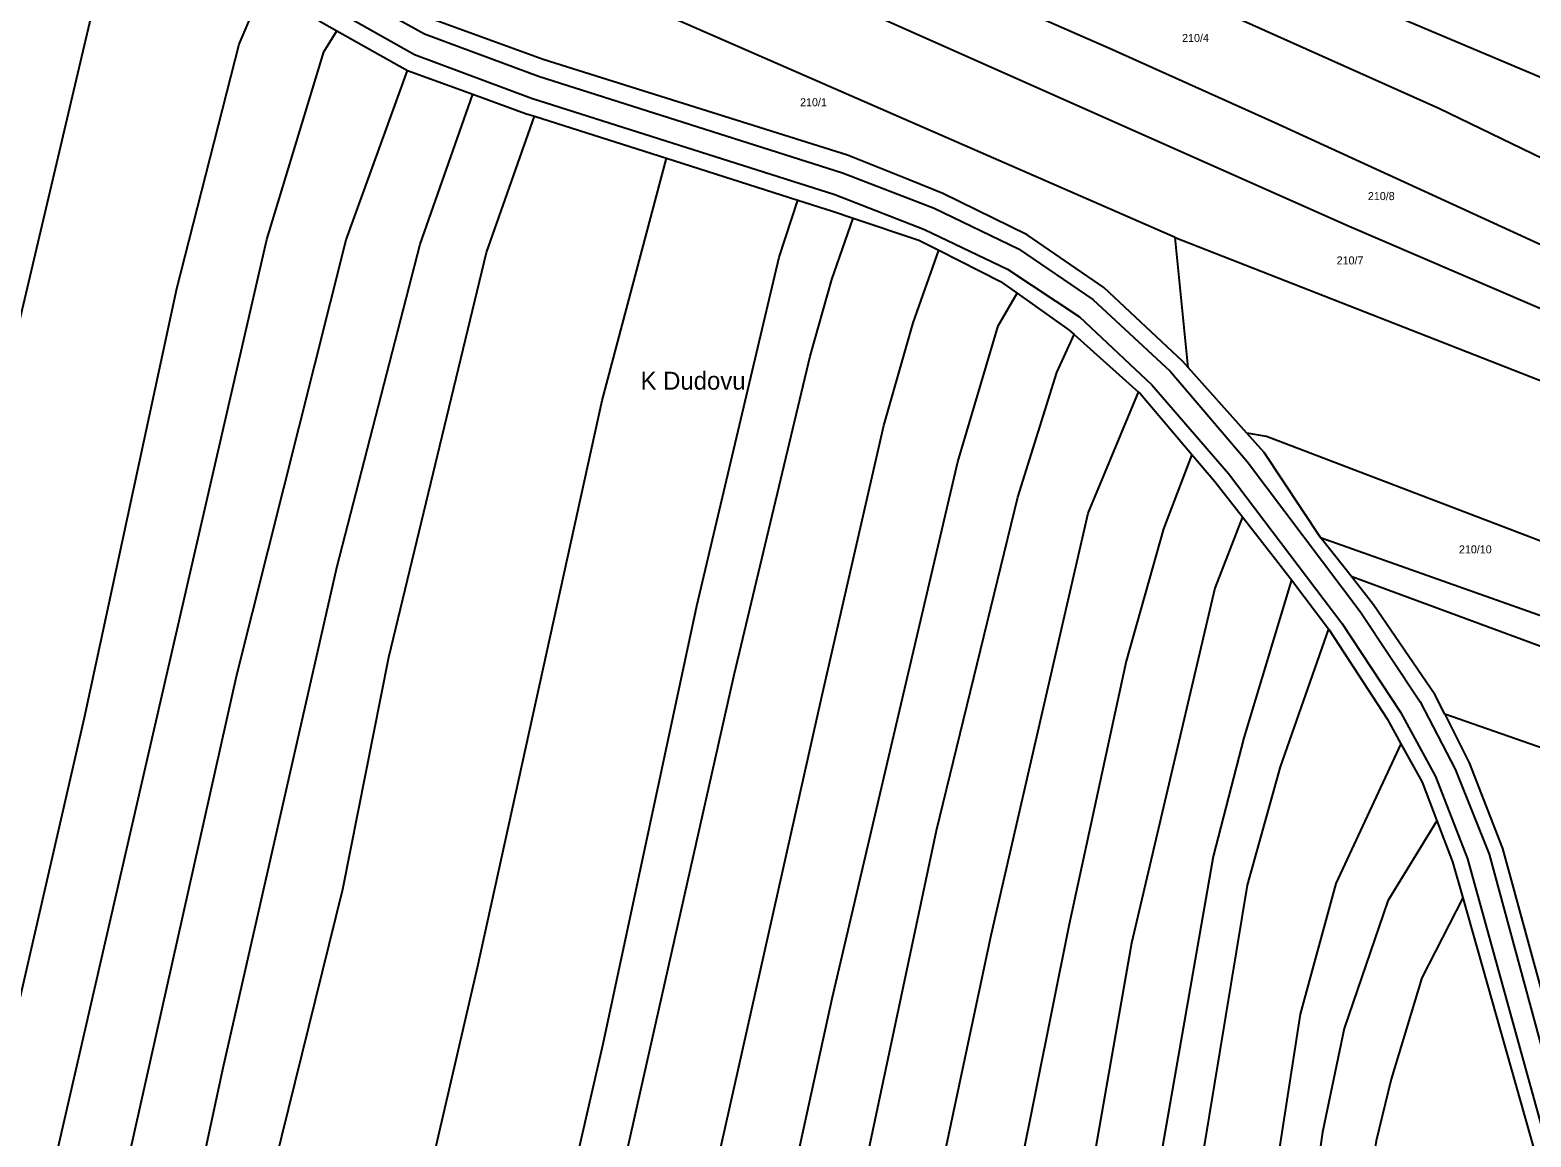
# Model space of a CAD drawing. Extents: x -744566 to -741843, y -1128407 to -1126744.
# Drawn here: x -743076.5 to -742757.6, y -1128024.5 to -1127789.3 of the extents above; entities that cross this region are included whole.
import ezdxf

# ---------------------------------------------------------------- set-up
doc = ezdxf.new("R2010")
doc.units = 0
for name, color, linetype in [('Hranice parcel', 7, 'Continuous'), ('Parcelní čísla', 7, 'Continuous'), ('Pop  PČ popisy', 7, 'Continuous'), ('Vnitřní kresba', 7, 'Continuous')]:
    doc.layers.add(name, color=color, linetype=linetype)

msp = doc.modelspace()

# ---------------------------------------------------------------- linework, layer by layer
at = {"layer": 'Hranice parcel'}
for p, q in [((-742833.19, -1127833.4), (-742972.27, -1127772.64)), ((-743011.33, -1127789.48), (-742996.28, -1127797.93)), ((-742996.28, -1127797.93), (-742982.41, -1127802.98)), ((-742969.31, -1127807.66), (-742941.27, -1127816.58)), ((-742941.27, -1127816.58), (-742913.36, -1127825.45)), ((-742830.43, -1127861.03), (-742833.19, -1127833.4)), ((-742854.64, -1127854.03), (-742840.94, -1127866.29)), ((-742817.94, -1127875.01), (-742830.43, -1127861.03)), ((-742802.25, -1127897.14), (-742686.17, -1127938.31)), ((-742795.76, -1127905.39), (-742802.25, -1127897.14)), ((-742808.46, -1127906.18), (-742800.6, -1127916.58)), ((-742795.76, -1127905.39), (-742687.4, -1127945.34)), ((-742698.39, -1127961.68), (-742775.86, -1127934.72)), ((-742772.05, -1127973.74), (-742745.25, -1128068.29))]:
    msp.add_line(p, q, dxfattribs=at)
for points in [[(-742705.33, -1127822.31), (-742752.11, -1127800.85), (-742855.88, -1127756.96), (-742856.57, -1127758.28), (-742916.95, -1127732.14)], [(-743134.48, -1128101.6), (-743116.84, -1128032.47), (-743112.87, -1128006.6), (-743093.99, -1127930.3), (-743081.3, -1127862.06), (-743057.88, -1127762.39), (-743049.21, -1127739.41)], [(-742929.76, -1127741.52), (-742892.25, -1127757.26), (-742839.56, -1127779.37), (-742839.56, -1127777.92), (-742777.16, -1127805.95), (-742712.92, -1127837.01)], [(-742942.9, -1127751.14), (-742921.78, -1127760.46), (-742847.12, -1127793.15), (-742812.02, -1127809), (-742724.3, -1127849.19), (-742701.43, -1127856.81), (-742666.84, -1127871.89)], [(-742670.28, -1127883.77), (-742733.59, -1127858.01), (-742796.71, -1127830.89), (-742912.22, -1127779.41), (-742955.04, -1127760.03)], [(-743103, -1128100.87), (-743064.96, -1127935.44), (-743045.29, -1127844.24), (-743032.09, -1127792.31), (-743025.38, -1127776.65)], [(-743025.38, -1127776.65), (-743015.05, -1127787.39), (-743011.33, -1127789.48)], [(-742830.43, -1127861.03), (-742831.55, -1127859.78), (-742848.33, -1127844.01), (-742864.61, -1127832.85), (-742882.56, -1127824.07), (-742889.66, -1127821.18), (-742902.77, -1127815.89), (-742967.48, -1127795.61), (-742991.64, -1127786.82)], [(-743087.22, -1128100.5), (-743078.12, -1128059.75), (-743051.52, -1127944.14), (-743026.17, -1127833.83), (-743014.07, -1127793.96), (-743011.33, -1127789.48)], [(-743071.48, -1128100.13), (-743055.35, -1128028.26), (-743032.57, -1127926.34), (-743009.32, -1127833.88), (-742996.28, -1127797.93)], [(-743054.77, -1128099.74), (-743035.44, -1128009.87), (-743011.3, -1127903.56), (-742993.62, -1127834.86), (-742982.41, -1127802.98)], [(-742982.41, -1127802.98), (-742971.25, -1127807.04), (-742969.31, -1127807.66)], [(-743039.34, -1128099.38), (-743028.83, -1128047.9), (-743010.01, -1127971.9), (-743000.24, -1127922.55), (-742979.49, -1127836.62), (-742969.31, -1127807.66)], [(-743006.9, -1128098.63), (-742981.41, -1127988.5), (-742954.92, -1127868.05), (-742941.27, -1127816.58)], [(-742976.11, -1128097.91), (-742954.73, -1128004.76), (-742934.78, -1127911.65), (-742917.32, -1127837.6), (-742913.36, -1127825.45)], [(-742913.36, -1127825.45), (-742905.98, -1127827.8), (-742901.58, -1127829.29)], [(-742965.39, -1128097.66), (-742926.85, -1127926.34), (-742910.73, -1127858.59), (-742906.15, -1127842.32), (-742901.58, -1127829.29)], [(-742901.58, -1127829.29), (-742887.63, -1127833.99), (-742883.39, -1127836.13)], [(-742833.19, -1127833.4), (-742726.08, -1127875.32), (-742678.13, -1127896.57), (-742675.1, -1127891.02)], [(-742945.48, -1128097.2), (-742908.25, -1127930.92), (-742895.08, -1127873.37), (-742888.84, -1127851.53), (-742883.39, -1127836.13)], [(-742883.39, -1127836.13), (-742870.31, -1127842.73), (-742866.75, -1127845.26)], [(-742928.33, -1128096.8), (-742906.05, -1127995.14), (-742879.36, -1127881.1), (-742870.77, -1127852.17), (-742866.75, -1127845.26)], [(-742866.75, -1127845.26), (-742855.66, -1127853.11), (-742854.64, -1127854.03)], [(-742912.92, -1128096.44), (-742883.88, -1127959.44), (-742866.58, -1127888.59), (-742858.3, -1127862.06), (-742854.64, -1127854.03)], [(-742896.59, -1128096.06), (-742872.27, -1127981.64), (-742851.64, -1127891.97), (-742840.94, -1127866.29)], [(-742840.94, -1127866.29), (-742840.54, -1127866.65), (-742829.62, -1127879.49)], [(-742683.5, -1127925.44), (-742813.75, -1127875.71), (-742817.94, -1127875.01)], [(-742802.25, -1127897.14), (-742814.27, -1127879.12), (-742817.94, -1127875.01)], [(-742829.62, -1127879.49), (-742835.64, -1127895.32), (-742843.58, -1127923.46), (-742855.73, -1127979.68), (-742869.71, -1128049.18), (-742880.65, -1128096.32)], [(-742829.62, -1127879.49), (-742824.72, -1127885.25), (-742818.84, -1127892.78)], [(-742818.84, -1127892.78), (-742824.75, -1127907.89), (-742842.47, -1127983.35), (-742854.91, -1128054.54), (-742864.87, -1128098.1)], [(-742818.84, -1127892.78), (-742810.82, -1127903.05), (-742808.46, -1127906.18)], [(-742808.46, -1127906.18), (-742818.57, -1127939.73), (-742825.08, -1127964.96), (-742840.18, -1128051.28), (-742849.78, -1128099.8)], [(-742775.86, -1127934.72), (-742777.97, -1127930.5), (-742791.02, -1127911.43), (-742795.76, -1127905.39)], [(-742800.6, -1127916.58), (-742810.82, -1127945.91), (-742817.85, -1127971.05), (-742831.77, -1128055.15), (-742841.14, -1128100.77)], [(-742800.6, -1127916.58), (-742800.46, -1127916.77), (-742788.13, -1127935.67), (-742785.19, -1127941)], [(-742775.86, -1127934.72), (-742770.7, -1127945.05), (-742763.59, -1127963.24), (-742744.12, -1128034.5), (-742737.18, -1128060.8)], [(-742785.19, -1127941), (-742799.05, -1127970.68), (-742806.6, -1127998.43), (-742816.93, -1128065.15), (-742824.28, -1128103)], [(-742785.19, -1127941), (-742780.69, -1127949.15), (-742777.55, -1127957.37)], [(-742777.55, -1127957.37), (-742787.96, -1127974.34), (-742797.26, -1128001.5), (-742801.83, -1128023.54), (-742807.9, -1128066.04), (-742814.65, -1128104.35)], [(-742777.55, -1127957.37), (-742774.23, -1127966.04), (-742772.05, -1127973.74)], [(-742772.05, -1127973.74), (-742780.73, -1127990.76), (-742787.24, -1128012.25), (-742790.44, -1128025.37), (-742802.94, -1128105.99)]]:
    msp.add_lwpolyline(points, dxfattribs=at)
at = {"layer": 'Vnitřní kresba'}
for p, q in [((-743008.52, -1127781.37), (-742992.69, -1127790.12)), ((-743012.17, -1127784.72), (-742994.83, -1127794.53)), ((-742992.69, -1127790.12), (-742968.49, -1127799.16)), ((-742994.83, -1127794.53), (-742969.96, -1127803.78)), ((-742968.49, -1127799.16), (-742903.86, -1127819.67)), ((-742969.96, -1127803.78), (-742905.49, -1127824.29)), ((-742903.86, -1127819.67), (-742884.37, -1127827.16)), ((-742905.49, -1127824.29), (-742886.43, -1127831.69)), ((-742884.37, -1127827.16), (-742866.45, -1127835.83)), ((-742886.43, -1127831.69), (-742868.83, -1127840.11)), ((-742866.45, -1127835.83), (-742850.65, -1127846.58)), ((-742868.83, -1127840.11), (-742853.46, -1127850.3)), ((-742850.65, -1127846.58), (-742834.26, -1127861.78)), ((-742853.46, -1127850.3), (-742838.11, -1127864.73)), ((-742834.26, -1127861.78), (-742817.86, -1127880.99)), ((-742838.11, -1127864.73), (-742821.82, -1127883.53)), ((-742817.86, -1127880.99), (-742793.88, -1127912.91)), ((-742821.82, -1127883.53), (-742797.76, -1127915.33)), ((-742793.88, -1127912.91), (-742781.08, -1127932.06)), ((-742797.76, -1127915.33), (-742785.31, -1127934.27)), ((-742781.08, -1127932.06), (-742773.68, -1127946.37)), ((-742785.31, -1127934.27), (-742777.87, -1127947.95)), ((-742777.87, -1127947.95), (-742771.04, -1127965.41)), ((-742773.68, -1127946.37), (-742766.43, -1127964.48)), ((-742766.43, -1127964.48), (-742738.98, -1128066.02)), ((-742771.04, -1127965.41), (-742742.76, -1128067.85))]:
    msp.add_line(p, q, dxfattribs=at)

# ---------------------------------------------------------------- texts
at = {"layer": 'Parcelní čísla'}
for s, p in [('210/4', (-742831.69, -1127791.86)), ('210/1', (-742912.87, -1127805.52)), ('210/8', (-742792.21, -1127825.46)), ('210/7', (-742798.85, -1127839.13)), ('210/10', (-742772.86, -1127900.53))]:
    msp.add_text(s, height=1.7, dxfattribs=at).set_placement(p)
at = {"layer": 'Pop  PČ popisy'}
msp.add_text('K Dudovu', height=3.8, dxfattribs=at).set_placement((-742946.77, -1127865.74))

doc.saveas('drawing.dxf')
